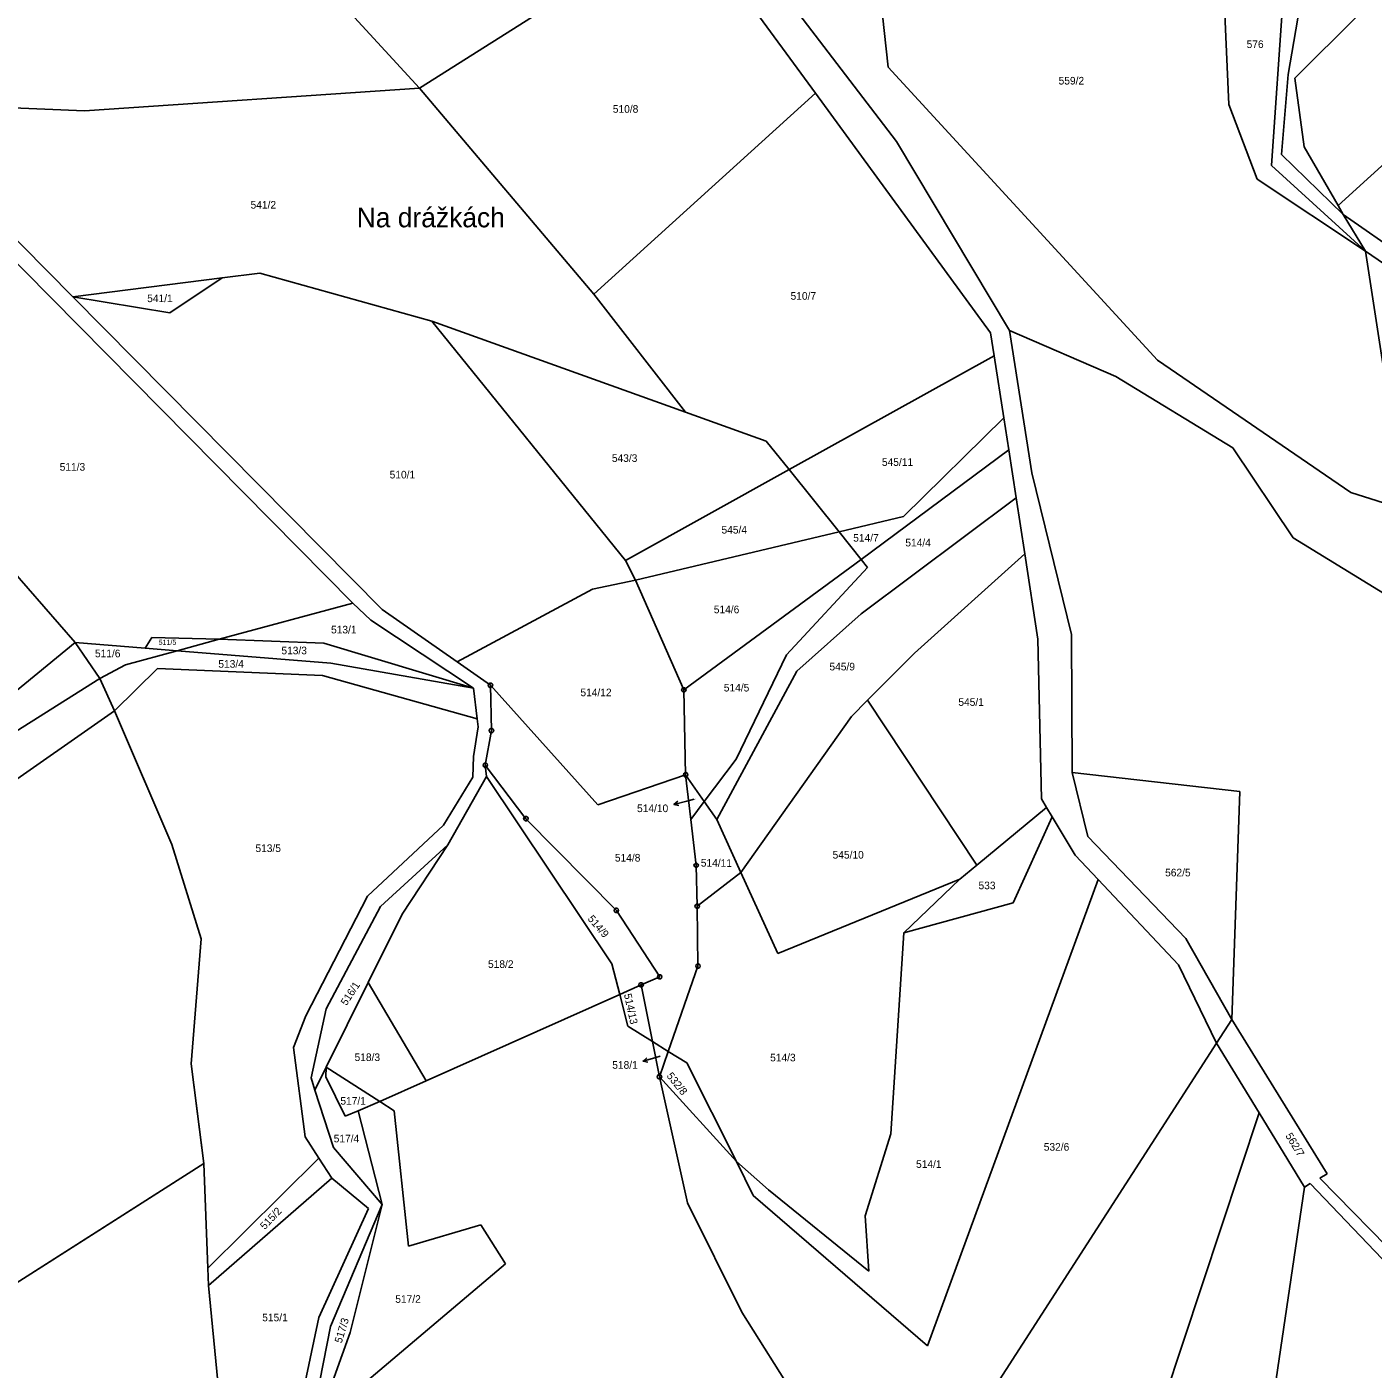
# Model space of a CAD drawing. Extents: x -593358 to -590116, y -1072518 to -1068420.
# Drawn here: x -591348.6 to -591048.4, y -1071922.2 to -1071622.8 of the extents above; entities that cross this region are included whole.
import ezdxf

# ---------------------------------------------------------------- set-up
doc = ezdxf.new("R2010")
doc.units = 0
for name, color, linetype in [('lesy', 7, 'Continuous'), ('Názvosloví', 7, 'Continuous'), ('Parcela KN', 7, 'Continuous'), ('Parcela ZE', 7, 'Continuous'), ('Parcelní číslo', 7, 'Continuous'), ('Vrstva 16', 7, 'Continuous'), ('Vrstva 24', 7, 'Continuous')]:
    doc.layers.add(name, color=color, linetype=linetype)

msp = doc.modelspace()

# ---------------------------------------------------------------- linework, layer by layer
at = {"layer": 'lesy'}
for points in [[(-591129.41, -1071549.64), (-591116.49, -1071569.55), (-591081.49, -1071619.93), (-591080.6, -1071640.12), (-591074.27, -1071656.72), (-591050.09, -1071672.8)], [(-591309.18, -1071876.35), (-591310.59, -1071865.21), (-591312, -1071854.07), (-591309.78, -1071826.23), (-591316.28, -1071805.2), (-591329.09, -1071775.34)], [(-591445.01, -1071838.65), (-591446.54, -1071824.7), (-591435.71, -1071850.885), (-591424.88, -1071877.07), (-591413.68, -1071904.15), (-591401.39, -1071934.26), (-591366.29, -1071912.68), (-591337.735, -1071894.515), (-591309.18, -1071876.35)], [(-591308.14, -1071903.51), (-591308.29, -1071899.69), (-591308.735, -1071888.02), (-591309.18, -1071876.35)], [(-591308.14, -1071903.51), (-591294.395, -1071891.57), (-591280.65, -1071879.63)], [(-591308.14, -1071903.51), (-591306.06, -1071924.99), (-591290.33, -1071958.38)]]:
    msp.add_lwpolyline(points, dxfattribs=at)
at = {"layer": 'Parcela KN'}
for p, q in [((-591057.55, -1071576.38), (-591067.34, -1071633.4)), ((-591056.22, -1071662.64), (-590965.16, -1071579.54)), ((-591162.02, -1071582.15), (-591156.54, -1071631.79)), ((-591154.73, -1071648.38), (-591200.64, -1071588.13)), ((-591066.5, -1071586.69), (-591071.03, -1071653.67)), ((-591201.27, -1071598.58), (-591172.76, -1071637.59)), ((-591080.6, -1071640.12), (-591081.49, -1071619.93)), ((-591051.73, -1071620.17), (-591065.88, -1071634.25)), ((-591156.54, -1071631.79), (-591096.5, -1071697.15)), ((-591067.34, -1071633.4), (-591068.85, -1071651.26)), ((-591065.88, -1071634.25), (-591063.78, -1071649.51)), ((-591172.76, -1071637.59), (-591133.7, -1071691.02)), ((-591074.27, -1071656.72), (-591080.6, -1071640.12)), ((-591129.49, -1071690.51), (-591154.73, -1071648.38)), ((-591055.06, -1071664.66), (-591068.85, -1071651.26)), ((-591063.78, -1071649.51), (-591056.22, -1071662.64)), ((-591071.03, -1071653.67), (-591050.09, -1071672.8)), ((-591050.09, -1071672.8), (-591074.27, -1071656.72)), ((-591363.88, -1071662.35), (-591275.95, -1071751.3)), ((-591338.4, -1071682.97), (-591357.12, -1071664.05)), ((-591056.22, -1071662.64), (-591055.06, -1071664.66)), ((-591050.09, -1071672.8), (-591055.06, -1071664.66)), ((-591041.27, -1071730.51), (-591050.09, -1071672.8)), ((-591269.43, -1071752.71), (-591338.4, -1071682.97)), ((-591133.7, -1071691.02), (-591132.9, -1071696.17)), ((-591105.77, -1071700.75), (-591129.49, -1071690.51)), ((-591129.49, -1071690.51), (-591124.48, -1071722.26)), ((-591132.9, -1071696.17), (-591178.65, -1071721.55)), ((-591132.9, -1071696.17), (-591130.77, -1071709.96)), ((-591096.5, -1071697.15), (-591053.4, -1071726.62)), ((-591079.66, -1071716.66), (-591105.77, -1071700.75)), ((-591153.13, -1071732.02), (-591130.77, -1071709.96)), ((-591130.77, -1071709.96), (-591129.66, -1071717.13)), ((-591129.66, -1071717.13), (-591128.01, -1071727.86)), ((-591066.25, -1071736.77), (-591079.66, -1071716.66)), ((-591178.65, -1071721.55), (-591215.12, -1071741.78)), ((-591124.48, -1071722.26), (-591115.64, -1071758.34)), ((-591053.4, -1071726.62), (-591041.27, -1071730.51)), ((-591162.6, -1071753.74), (-591128.01, -1071727.86)), ((-591128.01, -1071727.86), (-591126.08, -1071740.32)), ((-591167.51, -1071735.43), (-591153.13, -1071732.02)), ((-591212.88, -1071746.18), (-591167.51, -1071735.43)), ((-591040.18, -1071752.76), (-591066.25, -1071736.77)), ((-591215.12, -1071741.78), (-591212.88, -1071746.18)), ((-591126.08, -1071740.32), (-591123.14, -1071759.36)), ((-591222.51, -1071748.19), (-591252.71, -1071764.42)), ((-591212.88, -1071746.18), (-591222.51, -1071748.19)), ((-591305.72, -1071759.38), (-591275.95, -1071751.3)), ((-591275.95, -1071751.3), (-591271.95, -1071755.14)), ((-591252.71, -1071764.42), (-591269.43, -1071752.71)), ((-591176.89, -1071766.5), (-591162.6, -1071753.74)), ((-591271.95, -1071755.14), (-591249.04, -1071770.26)), ((-591315.15, -1071761.94), (-591305.72, -1071759.38)), ((-591123.14, -1071759.36), (-591122.37, -1071794.96)), ((-591115.64, -1071758.34), (-591115.52, -1071789.11)), ((-591326.64, -1071765.06), (-591315.15, -1071761.94)), ((-591332.39, -1071768.16), (-591326.64, -1071765.06)), ((-591245.25, -1071769.65), (-591252.71, -1071764.42)), ((-591332.39, -1071768.16), (-591380.82, -1071798.64)), ((-591329.09, -1071775.34), (-591332.39, -1071768.16)), ((-591194.77, -1071799.57), (-591176.89, -1071766.5)), ((-591249.04, -1071770.26), (-591248.2, -1071777.1)), ((-591245.25, -1071769.65), (-591245.02, -1071779.77)), ((-591329.09, -1071775.34), (-591363.48, -1071799.36)), ((-591327.97, -1071777.95), (-591329.09, -1071775.34)), ((-591316.28, -1071805.2), (-591327.97, -1071777.95)), ((-591248.2, -1071777.1), (-591247.98, -1071778.93)), ((-591247.98, -1071778.93), (-591249.01, -1071785.56)), ((-591245.02, -1071779.77), (-591246.4, -1071787.5)), ((-591249.17, -1071790.18), (-591249.01, -1071785.56)), ((-591255.74, -1071800.88), (-591249.17, -1071790.18)), ((-591254.74, -1071805.21), (-591246.15, -1071790.03)), ((-591246.15, -1071790.03), (-591246.4, -1071787.5)), ((-591218.15, -1071831.82), (-591246.15, -1071790.03)), ((-591115.52, -1071789.11), (-591112.03, -1071803.35)), ((-591078.12, -1071793.34), (-591115.52, -1071789.11)), ((-591079.9, -1071844.22), (-591078.12, -1071793.34)), ((-591122.37, -1071794.96), (-591121.21, -1071796.89)), ((-591121.21, -1071796.89), (-591136.76, -1071809.75)), ((-591121.21, -1071796.89), (-591119.96, -1071798.97)), ((-591119.96, -1071798.97), (-591114.82, -1071807.51)), ((-591272.66, -1071816.7), (-591255.74, -1071800.88)), ((-591189.39, -1071811.38), (-591194.77, -1071799.57)), ((-591309.78, -1071826.23), (-591316.28, -1071805.2)), ((-591269.78, -1071819.01), (-591254.74, -1071805.21)), ((-591254.74, -1071805.21), (-591264.95, -1071820.68)), ((-591112.03, -1071803.35), (-591090.16, -1071826.16)), ((-591114.82, -1071807.51), (-591109.7, -1071812.97)), ((-591181.15, -1071829.45), (-591189.39, -1071811.38)), ((-591136.76, -1071809.75), (-591140.59, -1071812.91)), ((-591140.59, -1071812.91), (-591181.15, -1071829.45)), ((-591109.7, -1071812.97), (-591147.77, -1071917.03)), ((-591109.7, -1071812.97), (-591091.82, -1071832.03)), ((-591286.41, -1071843.37), (-591272.66, -1071816.7)), ((-591281.9, -1071841.84), (-591269.78, -1071819.01)), ((-591264.95, -1071820.68), (-591272.52, -1071835.92)), ((-591312, -1071854.07), (-591309.78, -1071826.23)), ((-591090.16, -1071826.16), (-591079.9, -1071844.22)), ((-591216.41, -1071838.6), (-591218.15, -1071831.82)), ((-591091.82, -1071832.03), (-591083.3, -1071849.49)), ((-591272.52, -1071835.92), (-591281.91, -1071854.84)), ((-591272.52, -1071835.92), (-591259.57, -1071857.88)), ((-591216.41, -1071838.6), (-591259.57, -1071857.88)), ((-591214.59, -1071845.69), (-591216.41, -1071838.6)), ((-591289.16, -1071850.48), (-591286.41, -1071843.37)), ((-591285.26, -1071857.21), (-591281.9, -1071841.84)), ((-591079.9, -1071844.22), (-591083.3, -1071849.49)), ((-591209.13, -1071849.12), (-591214.59, -1071845.69)), ((-591205.6, -1071851.33), (-591209.13, -1071849.12)), ((-591083.3, -1071849.49), (-591155.95, -1071962.17)), ((-591286.58, -1071870.41), (-591289.16, -1071850.48)), ((-591207.56, -1071856.98), (-591205.6, -1071851.33)), ((-591201.44, -1071853.83), (-591205.6, -1071851.33)), ((-591309.18, -1071876.35), (-591312, -1071854.07)), ((-591281.91, -1071854.84), (-591284.44, -1071859.95)), ((-591269.93, -1071862.5), (-591281.91, -1071854.84)), ((-591190.41, -1071875.9), (-591201.44, -1071853.83)), ((-591284.44, -1071859.95), (-591285.26, -1071857.21)), ((-591259.57, -1071857.88), (-591269.93, -1071862.5)), ((-591201.28, -1071885.07), (-591207.56, -1071856.98)), ((-591280.26, -1071872.75), (-591284.44, -1071859.95)), ((-591269.93, -1071862.5), (-591266.7, -1071864.58)), ((-591266.7, -1071864.58), (-591263.54, -1071894.78)), ((-591286.58, -1071870.41), (-591283.53, -1071875.16)), ((-591269.38, -1071885.45), (-591280.26, -1071872.75)), ((-591366.29, -1071912.68), (-591309.18, -1071876.35)), ((-591309.18, -1071876.35), (-591308.29, -1071899.69)), ((-591308.29, -1071899.69), (-591283.53, -1071875.16)), ((-591283.53, -1071875.16), (-591280.65, -1071879.63)), ((-591186.63, -1071883.45), (-591190.41, -1071875.9)), ((-591308.14, -1071903.51), (-591280.65, -1071879.63)), ((-591280.65, -1071879.63), (-591272.48, -1071886.36)), ((-591283.51, -1071910.71), (-591272.48, -1071886.36)), ((-591280.93, -1071912.65), (-591269.38, -1071885.45)), ((-591189.19, -1071909.47), (-591201.28, -1071885.07)), ((-591147.77, -1071917.03), (-591186.63, -1071883.45)), ((-591263.54, -1071894.78), (-591247.43, -1071889.97)), ((-591247.43, -1071889.97), (-591241.86, -1071898.7)), ((-591308.29, -1071899.69), (-591308.14, -1071903.51)), ((-591241.86, -1071898.7), (-591283.69, -1071934)), ((-591308.14, -1071903.51), (-591306.06, -1071924.99)), ((-591160.75, -1071954.57), (-591189.19, -1071909.47)), ((-591289.98, -1071940.95), (-591283.51, -1071910.71)), ((-591286.79, -1071942.39), (-591280.93, -1071912.65))]:
    msp.add_line(p, q, dxfattribs=at)
at = {"layer": 'Parcela ZE'}
for p, q in [((-591297.38, -1071596.97), (-591261.05, -1071636.45)), ((-591261.05, -1071636.45), (-591201.27, -1071598.58)), ((-591335.82, -1071641.48), (-591261.05, -1071636.45)), ((-591261.05, -1071636.45), (-591222.23, -1071682.43)), ((-591385.94, -1071639.55), (-591335.82, -1071641.48)), ((-591222.23, -1071682.43), (-591172.76, -1071637.59)), ((-591055.06, -1071664.66), (-590983.17, -1071714.95)), ((-591050.09, -1071672.8), (-590983.8, -1071718.49)), ((-591305.07, -1071678.79), (-591338.4, -1071682.97)), ((-591316.73, -1071686.55), (-591305.07, -1071678.79)), ((-591296.67, -1071677.74), (-591305.07, -1071678.79)), ((-591258.29, -1071688.41), (-591296.67, -1071677.74)), ((-591338.4, -1071682.97), (-591316.73, -1071686.55)), ((-591222.23, -1071682.43), (-591201.78, -1071708.7)), ((-591258.29, -1071688.41), (-591215.12, -1071741.78)), ((-591201.78, -1071708.7), (-591258.29, -1071688.41)), ((-591183.77, -1071715.17), (-591201.78, -1071708.7)), ((-591183.77, -1071715.17), (-591178.65, -1071721.55)), ((-591162.55, -1071741.6), (-591129.66, -1071717.13)), ((-591178.65, -1071721.55), (-591167.51, -1071735.43)), ((-591363.45, -1071730.78), (-591337.9, -1071760.12)), ((-591167.51, -1071735.43), (-591162.55, -1071741.6)), ((-591202.12, -1071770.68), (-591162.55, -1071741.6)), ((-591162.55, -1071741.6), (-591161.13, -1071743.35)), ((-591150.71, -1071762.45), (-591126.08, -1071740.32)), ((-591161.13, -1071743.35), (-591179.26, -1071762.85)), ((-591202.12, -1071770.68), (-591212.88, -1071746.18)), ((-591383.05, -1071797.18), (-591337.9, -1071760.12)), ((-591337.9, -1071760.12), (-591332.39, -1071768.16)), ((-591337.9, -1071760.12), (-591322.24, -1071761.37)), ((-591320.74, -1071758.96), (-591322.24, -1071761.37)), ((-591305.72, -1071759.38), (-591320.74, -1071758.96)), ((-591282.41, -1071760.22), (-591305.72, -1071759.38)), ((-591249.04, -1071770.26), (-591282.41, -1071760.22)), ((-591322.24, -1071761.37), (-591315.15, -1071761.94)), ((-591315.15, -1071761.94), (-591280.86, -1071764.69)), ((-591179.26, -1071762.85), (-591190.43, -1071786.13)), ((-591161.13, -1071773), (-591150.71, -1071762.45)), ((-591329.09, -1071775.34), (-591319.52, -1071765.92)), ((-591319.52, -1071765.92), (-591282.69, -1071767.44)), ((-591280.86, -1071764.69), (-591249.04, -1071770.26)), ((-591282.69, -1071767.44), (-591248.2, -1071777.1)), ((-591245.25, -1071769.65), (-591221.34, -1071796.33)), ((-591201.72, -1071789.61), (-591202.12, -1071770.68)), ((-591164.71, -1071776.63), (-591161.13, -1071773)), ((-591161.13, -1071773), (-591136.76, -1071809.75)), ((-591189.39, -1071811.38), (-591164.71, -1071776.63)), ((-591190.43, -1071786.13), (-591197.56, -1071795.57)), ((-591246.4, -1071787.5), (-591237.34, -1071799.41)), ((-591221.34, -1071796.33), (-591201.72, -1071789.61)), ((-591197.56, -1071795.57), (-591201.72, -1071789.61)), ((-591200.56, -1071799.62), (-591201.72, -1071789.61)), ((-591197.56, -1071795.57), (-591200.56, -1071799.62)), ((-591194.77, -1071799.57), (-591197.56, -1071795.57)), ((-591128.69, -1071818.16), (-591119.96, -1071798.97)), ((-591237.34, -1071799.41), (-591217.16, -1071819.88)), ((-591199.37, -1071809.82), (-591200.56, -1071799.62)), ((-591199.13, -1071818.93), (-591199.37, -1071809.82)), ((-591199.13, -1071818.93), (-591189.39, -1071811.38)), ((-591140.59, -1071812.91), (-591153.08, -1071824.9)), ((-591217.16, -1071819.88), (-591207.5, -1071834.68)), ((-591198.97, -1071832.29), (-591199.13, -1071818.93)), ((-591153.08, -1071824.9), (-591128.69, -1071818.16)), ((-591153.08, -1071824.9), (-591155.98, -1071869.67)), ((-591205.6, -1071851.33), (-591198.97, -1071832.29)), ((-591207.5, -1071834.68), (-591211.65, -1071836.47)), ((-591211.65, -1071836.47), (-591216.41, -1071838.6)), ((-591211.65, -1071836.47), (-591209.13, -1071849.12)), ((-591079.9, -1071844.22), (-591058.66, -1071878.6)), ((-591209.13, -1071849.12), (-591207.56, -1071856.98)), ((-591073.81, -1071865.02), (-591083.3, -1071849.49)), ((-591281.96, -1071856.96), (-591281.91, -1071854.84)), ((-591277.64, -1071865.79), (-591281.96, -1071856.96)), ((-591190.41, -1071875.9), (-591207.56, -1071856.98)), ((-591274.79, -1071864.57), (-591277.64, -1071865.79)), ((-591269.93, -1071862.5), (-591274.79, -1071864.57)), ((-591269.38, -1071885.45), (-591274.79, -1071864.57)), ((-591122.27, -1072010.92), (-591073.81, -1071865.02)), ((-591063.7, -1071881.58), (-591073.81, -1071865.02)), ((-591155.98, -1071869.67), (-591161.66, -1071888)), ((-591183.22, -1071882.19), (-591190.41, -1071875.9)), ((-591058.66, -1071878.6), (-591060.29, -1071879.57)), ((-591060.29, -1071879.57), (-591023.92, -1071916.85)), ((-591160.83, -1071900.31), (-591183.22, -1071882.19)), ((-591063.7, -1071881.58), (-591089.65, -1072056.69)), ((-591062.41, -1071880.82), (-591063.7, -1071881.58)), ((-591025.62, -1071919.37), (-591062.41, -1071880.82)), ((-591276.55, -1071914), (-591269.38, -1071885.45)), ((-591161.66, -1071888), (-591160.83, -1071900.31)), ((-591283.69, -1071934), (-591276.55, -1071914))]:
    msp.add_line(p, q, dxfattribs=at)
at = {"layer": 'Vrstva 16'}
for p, q in [((-591204.323, -1071796.237), (-591201.42, -1071795.48)), ((-591199.79, -1071795.06), (-591201.42, -1071795.48)), ((-591211.226, -1071853.493), (-591208.35, -1071852.64)), ((-591207.42, -1071852.36), (-591208.35, -1071852.64))]:
    msp.add_line(p, q, dxfattribs=at)
for points in [[(-591203.229, -1071796.469), (-591204.323, -1071796.237), (-591203.481, -1071795.501)], [(-591210.125, -1071853.688), (-591211.226, -1071853.493), (-591210.41, -1071852.729)]]:
    msp.add_lwpolyline(points, dxfattribs=at)
at = {"layer": 'Vrstva 24'}
for p, q in [((-591245.37, -1071769.65), (-591245.13, -1071769.65)), ((-591202.24, -1071770.68), (-591202, -1071770.68)), ((-591245.14, -1071779.77), (-591244.9, -1071779.77)), ((-591246.52, -1071787.5), (-591246.28, -1071787.5)), ((-591201.84, -1071789.61), (-591201.6, -1071789.61)), ((-591237.46, -1071799.41), (-591237.22, -1071799.41)), ((-591199.49, -1071809.82), (-591199.25, -1071809.82)), ((-591217.28, -1071819.88), (-591217.04, -1071819.88)), ((-591199.25, -1071818.93), (-591199.01, -1071818.93)), ((-591199.09, -1071832.29), (-591198.85, -1071832.29)), ((-591207.62, -1071834.68), (-591207.38, -1071834.68)), ((-591211.77, -1071836.47), (-591211.53, -1071836.47)), ((-591207.68, -1071856.98), (-591207.44, -1071856.98))]:
    msp.add_line(p, q, dxfattribs=at)
for points in [[(-591245.1, -1071769.17), (-591244.85, -1071769.35), (-591244.75, -1071769.64), (-591244.85, -1071769.93), (-591245.1, -1071770.11), (-591245.41, -1071770.11), (-591245.66, -1071769.93), (-591245.76, -1071769.64), (-591245.66, -1071769.35), (-591245.41, -1071769.17)], [(-591201.97, -1071770.2), (-591201.72, -1071770.38), (-591201.62, -1071770.67), (-591201.72, -1071770.96), (-591201.97, -1071771.14), (-591202.28, -1071771.14), (-591202.53, -1071770.96), (-591202.63, -1071770.67), (-591202.53, -1071770.38), (-591202.28, -1071770.2)], [(-591244.87, -1071779.29), (-591244.62, -1071779.47), (-591244.52, -1071779.76), (-591244.62, -1071780.05), (-591244.87, -1071780.23), (-591245.18, -1071780.23), (-591245.43, -1071780.05), (-591245.53, -1071779.76), (-591245.43, -1071779.47), (-591245.18, -1071779.29)], [(-591246.25, -1071787.02), (-591246, -1071787.2), (-591245.9, -1071787.49), (-591246, -1071787.78), (-591246.25, -1071787.96), (-591246.56, -1071787.96), (-591246.81, -1071787.78), (-591246.91, -1071787.49), (-591246.81, -1071787.2), (-591246.56, -1071787.02)], [(-591201.57, -1071789.13), (-591201.32, -1071789.31), (-591201.22, -1071789.6), (-591201.32, -1071789.89), (-591201.57, -1071790.07), (-591201.88, -1071790.07), (-591202.13, -1071789.89), (-591202.23, -1071789.6), (-591202.13, -1071789.31), (-591201.88, -1071789.13)], [(-591237.19, -1071798.93), (-591236.94, -1071799.11), (-591236.84, -1071799.4), (-591236.94, -1071799.69), (-591237.19, -1071799.87), (-591237.5, -1071799.87), (-591237.75, -1071799.69), (-591237.85, -1071799.4), (-591237.75, -1071799.11), (-591237.5, -1071798.93)], [(-591199.22, -1071809.34), (-591198.97, -1071809.52), (-591198.87, -1071809.81), (-591198.97, -1071810.1), (-591199.22, -1071810.28), (-591199.53, -1071810.28), (-591199.78, -1071810.1), (-591199.88, -1071809.81), (-591199.78, -1071809.52), (-591199.53, -1071809.34)], [(-591217.01, -1071819.4), (-591216.76, -1071819.58), (-591216.66, -1071819.87), (-591216.76, -1071820.16), (-591217.01, -1071820.34), (-591217.32, -1071820.34), (-591217.57, -1071820.16), (-591217.67, -1071819.87), (-591217.57, -1071819.58), (-591217.32, -1071819.4)], [(-591198.98, -1071818.45), (-591198.73, -1071818.63), (-591198.63, -1071818.92), (-591198.73, -1071819.21), (-591198.98, -1071819.39), (-591199.29, -1071819.39), (-591199.54, -1071819.21), (-591199.64, -1071818.92), (-591199.54, -1071818.63), (-591199.29, -1071818.45)], [(-591198.82, -1071831.81), (-591198.57, -1071831.99), (-591198.47, -1071832.28), (-591198.57, -1071832.57), (-591198.82, -1071832.75), (-591199.13, -1071832.75), (-591199.38, -1071832.57), (-591199.48, -1071832.28), (-591199.38, -1071831.99), (-591199.13, -1071831.81)], [(-591207.35, -1071834.2), (-591207.1, -1071834.38), (-591207, -1071834.67), (-591207.1, -1071834.96), (-591207.35, -1071835.14), (-591207.66, -1071835.14), (-591207.91, -1071834.96), (-591208.01, -1071834.67), (-591207.91, -1071834.38), (-591207.66, -1071834.2)], [(-591211.5, -1071835.99), (-591211.25, -1071836.17), (-591211.15, -1071836.46), (-591211.25, -1071836.75), (-591211.5, -1071836.93), (-591211.81, -1071836.93), (-591212.06, -1071836.75), (-591212.16, -1071836.46), (-591212.06, -1071836.17), (-591211.81, -1071835.99)], [(-591207.41, -1071856.5), (-591207.16, -1071856.68), (-591207.06, -1071856.97), (-591207.16, -1071857.26), (-591207.41, -1071857.44), (-591207.72, -1071857.44), (-591207.97, -1071857.26), (-591208.07, -1071856.97), (-591207.97, -1071856.68), (-591207.72, -1071856.5)]]:
    msp.add_lwpolyline(points, close=True, dxfattribs=at)

# ---------------------------------------------------------------- texts
at = {"layer": 'Názvosloví'}
msp.add_text('Na drážkách', height=4.4, dxfattribs=at).set_placement((-591275.076, -1071667.49))
at = {"layer": 'Parcelní číslo'}
for s, height, p in [('576', 1.7, (-591076.611, -1071627.49)), ('559/2', 1.7, (-591118.541, -1071635.64)), ('510/8', 1.7, (-591217.959, -1071641.94)), ('541/2', 1.7, (-591298.746, -1071663.32)), ('510/7', 1.7, (-591178.319, -1071683.65)), ('541/1', 1.7, (-591321.804, -1071684.18)), ('543/3', 1.7, (-591218.174, -1071719.82)), ('511/3', 1.7, (-591341.321, -1071721.78)), ('545/11', 1.7, (-591157.95, -1071720.71)), ('510/1', 1.7, (-591267.731, -1071723.51)), ('545/4', 1.7, (-591193.727, -1071735.81)), ('514/7', 1.7, (-591164.352, -1071737.61)), ('514/4', 1.7, (-591152.722, -1071738.67)), ('514/6', 1.7, (-591195.442, -1071753.58)), ('513/1', 1.7, (-591280.801, -1071758.08)), ('511/5', 1.14, (-591319.248, -1071760.63)), ('511/6', 1.7, (-591333.454, -1071763.4)), ('513/3', 1.7, (-591291.876, -1071762.74)), ('513/4', 1.7, (-591305.939, -1071765.73)), ('545/9', 1.7, (-591169.647, -1071766.33)), ('514/5', 1.7, (-591193.209, -1071771.03)), ('514/12', 1.7, (-591225.187, -1071772.09)), ('545/1', 1.7, (-591140.899, -1071774.24)), ('514/10', 0.1, (-591199.996, -1071795.06)), ('513/5', 1.7, (-591297.666, -1071806.84)), ('514/8', 1.7, (-591217.502, -1071808.97)), ('545/10', 1.7, (-591168.945, -1071808.31)), ('562/5', 1.7, (-591094.791, -1071812.27)), ('533', 1.7, (-591136.405, -1071815.14)), ('518/2', 1.7, (-591245.792, -1071832.69)), ('518/3', 1.7, (-591275.556, -1071853.47)), ('518/1', 0.1, (-591207.585, -1071852.36)), ('514/3', 1.7, (-591182.879, -1071853.54)), ('517/1', 1.7, (-591278.724, -1071863.2)), ('517/4', 1.7, (-591280.212, -1071871.6)), ('532/6', 1.7, (-591121.851, -1071873.46)), ('514/1', 1.7, (-591150.334, -1071877.3)), ('517/2', 1.7, (-591266.476, -1071907.4)), ('515/1', 1.7, (-591296.151, -1071911.52))]:
    msp.add_text(s, height=height, dxfattribs=at).set_placement(p)
for s, rotation, p in [('514/11', 359.47372, (-591198.345, -1071810.091)), ('514/9', 310.8296, (-591223.678, -1071821.82)), ('516/1', 56.66553, (-591277.37, -1071841.236)), ('514/13', 282.12442, (-591215.488, -1071838.599)), ('532/8', 308.65236, (-591206.067, -1071856.821)), ('562/7', 301.31851, (-591068.026, -1071870.128)), ('515/2', 46.40958, (-591295.593, -1071891.206)), ('517/3', 73.05212, (-591278.447, -1071916.521))]:
    msp.add_text(s, height=1.7, rotation=rotation, dxfattribs=at).set_placement(p)
at = {"layer": 'Vrstva 16'}
for s, p in [('514/10', (-591212.558, -1071797.94)), ('518/1', (-591218.089, -1071855.19))]:
    msp.add_text(s, height=1.7, dxfattribs=at).set_placement(p)

doc.saveas('drawing.dxf')
